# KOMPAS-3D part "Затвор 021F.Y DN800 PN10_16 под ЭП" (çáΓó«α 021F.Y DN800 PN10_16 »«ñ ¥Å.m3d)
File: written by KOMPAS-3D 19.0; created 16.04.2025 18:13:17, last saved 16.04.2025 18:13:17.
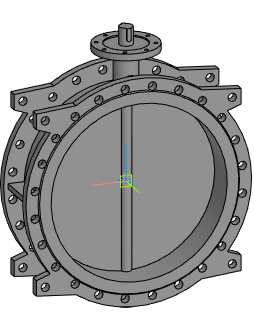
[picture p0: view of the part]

Document properties: Автор: Евгений; Полное имя файла: E:\Dendor Работа Сачек\3D для проекитирвщиков\1.6 Тип 021F.Y Затвор дисковый поворотный фланцевый\stp_Тип 021F.Y Затвор  DN40 PN10_16 под ЭП\Затвор 021F.Y DN800 PN10_16 под ЭП.m3d

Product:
- Part/product: Затвор 021F.Y DN800 PN10_16 под ЭП

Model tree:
1. Операция без истории:1  (labels: Затвор 021F.Y DN800 PN10_16 под ЭП)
